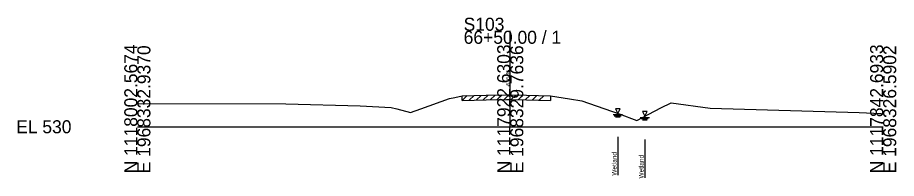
# Model space of a CAD drawing. Extents: x -26 to 163, y -10 to 45020.
# Drawn here: x -25.7 to 162.8, y 25488.9 to 25523.5 of the extents above; entities that cross this region are included whole.
import ezdxf

# ---------------------------------------------------------------- set-up
doc = ezdxf.new("R2010")
doc.units = 0
for name, color, linetype in [('RD_GPK_XS_Cell', 7, 'Continuous'), ('RD_XS_ExGround', 7, 'Continuous'), ('RD_XS_ExPaveRet', 7, 'Continuous'), ('RD_XS_EXWetland', 7, 'Continuous'), ('RD_XS_TX_Elev_EX', 7, 'Continuous')]:
    doc.layers.add(name, color=color, linetype=linetype)

msp = doc.modelspace()

# ---------------------------------------------------------------- linework, layer by layer
at = {"layer": 'RD_GPK_XS_Cell'}
for p, q in [((80, 25500), (80, 25520.62)), ((0, 25500), (80, 25500)), ((80, 25500), (160, 25500))]:
    msp.add_line(p, q, dxfattribs=at)
at = {"layer": 'RD_XS_ExGround'}
for p, q in [((68.11, 25506.28), (69.7, 25506.65)), ((69.7, 25506.65), (74.81, 25506.77)), ((74.81, 25506.77), (79.18, 25506.87)), ((79.18, 25506.87), (80, 25506.85)), ((80, 25506.85), (83.5, 25506.76)), ((83.5, 25506.76), (88.62, 25506.63)), ((88.62, 25506.63), (92.68, 25506.01)), ((0, 25505.02), (31.85, 25504.92)), ((31.85, 25504.92), (47.8, 25504.5)), ((60.83, 25503.88), (66.97, 25506.09)), ((66.97, 25506.09), (68.11, 25506.28)), ((92.68, 25506.01), (95.34, 25505.59)), ((95.34, 25505.59), (103.37, 25502.74)), ((112.29, 25504.05), (114.51, 25505.14)), ((114.51, 25505.14), (122.9, 25503.98)), ((47.8, 25504.5), (54.48, 25504.17)), ((54.48, 25504.17), (55.64, 25503.88)), ((55.64, 25503.88), (58.61, 25503.08)), ((58.61, 25503.08), (60.83, 25503.88)), ((107.13, 25501.36), (112.29, 25504.05)), ((122.9, 25503.98), (154.83, 25503.06)), ((154.83, 25503.06), (159.6, 25502.82)), ((159.6, 25502.82), (160, 25502.81)), ((103.37, 25502.74), (107.13, 25501.36))]:
    msp.add_line(p, q, dxfattribs=at)
at = {"layer": 'RD_XS_ExPaveRet'}
for p, q in [((69.7, 25505.65), (70.73, 25506.68)), ((69.7, 25505.65), (69.7, 25506.65)), ((71.2, 25505.69), (72.23, 25506.71)), ((72.7, 25505.72), (73.73, 25506.74)), ((74.2, 25505.75), (75.23, 25506.78)), ((75.7, 25505.79), (76.73, 25506.81)), ((77.2, 25505.83), (78.23, 25506.85)), ((78.7, 25505.86), (79.7, 25506.86)), ((80.2, 25505.85), (81.18, 25506.82)), ((81.7, 25505.81), (82.68, 25506.78)), ((83.2, 25505.77), (84.18, 25506.74)), ((84.7, 25505.73), (85.68, 25506.7)), ((86.2, 25505.69), (87.18, 25506.67)), ((88.62, 25506.63), (88.62, 25505.63)), ((69.7, 25505.65), (74.81, 25505.77)), ((74.81, 25505.77), (79.18, 25505.87)), ((79.18, 25505.87), (80, 25505.85)), ((80, 25505.85), (83.5, 25505.76)), ((83.5, 25505.76), (88.62, 25505.63))]:
    msp.add_line(p, q, dxfattribs=at)
at = {"layer": 'RD_XS_EXWetland'}
for p, q in [((102.55, 25503.86), (103.05, 25502.86)), ((103.55, 25503.86), (102.55, 25503.86)), ((103.05, 25502.86), (103.55, 25503.86)), ((108.34, 25503.25), (108.84, 25502.25)), ((109.34, 25503.25), (108.34, 25503.25)), ((108.84, 25502.25), (109.34, 25503.25)), ((102.05, 25502.61), (104.05, 25502.61)), ((102.3, 25502.36), (103.8, 25502.36)), ((102.55, 25502.11), (103.55, 25502.11)), ((107.84, 25502), (109.84, 25502)), ((108.09, 25501.75), (109.59, 25501.75)), ((108.34, 25501.5), (109.34, 25501.5)), ((103.05, 25497.86), (103.05, 25489.61)), ((108.84, 25497.25), (108.84, 25489))]:
    msp.add_line(p, q, dxfattribs=at)

# ---------------------------------------------------------------- texts
at = {"layer": 'RD_GPK_XS_Cell'}
for s, p in [('S103', (70, 25520.62)), ('66+50.00 / 1', (70, 25517.82)), ('EL 530', (-26, 25498.6))]:
    msp.add_text(s, height=2.8, dxfattribs=at).set_placement(p)
for s, p in [('N 1118002.5674', (0, 25490)), ('E 1968332.9370', (2.8, 25490)), ('N 1117922.6303', (80, 25490)), ('E 1968329.7636', (82.8, 25490)), ('N 1117842.6933', (160, 25490)), ('E 1968326.5902', (162.8, 25490))]:
    msp.add_text(s, height=2.8, rotation=90, dxfattribs=at).set_placement(p)
at = {"layer": 'RD_XS_EXWetland'}
for p in [(102.8, 25489.5), (108.59, 25488.89)]:
    msp.add_text('Wetland ', height=1, rotation=90, dxfattribs=at).set_placement(p)
at = {"layer": 'RD_XS_TX_Elev_EX'}
msp.add_text('536.85', height=0.8, rotation=90, dxfattribs=at).set_placement((79.9, 25508.85))

doc.saveas('drawing.dxf')
